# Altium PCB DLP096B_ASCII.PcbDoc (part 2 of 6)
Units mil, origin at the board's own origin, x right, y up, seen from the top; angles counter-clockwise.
Board outline 4950 x 3159.45 mil, 8 copper layers (Top Layer, GND1, SIGNAL1, POWER1, POWER2, SIGNAL2, GND2, Bottom Layer), stack 60.4 mil thick; 327 components, 222 nets, 1374 pads, 853 vias.
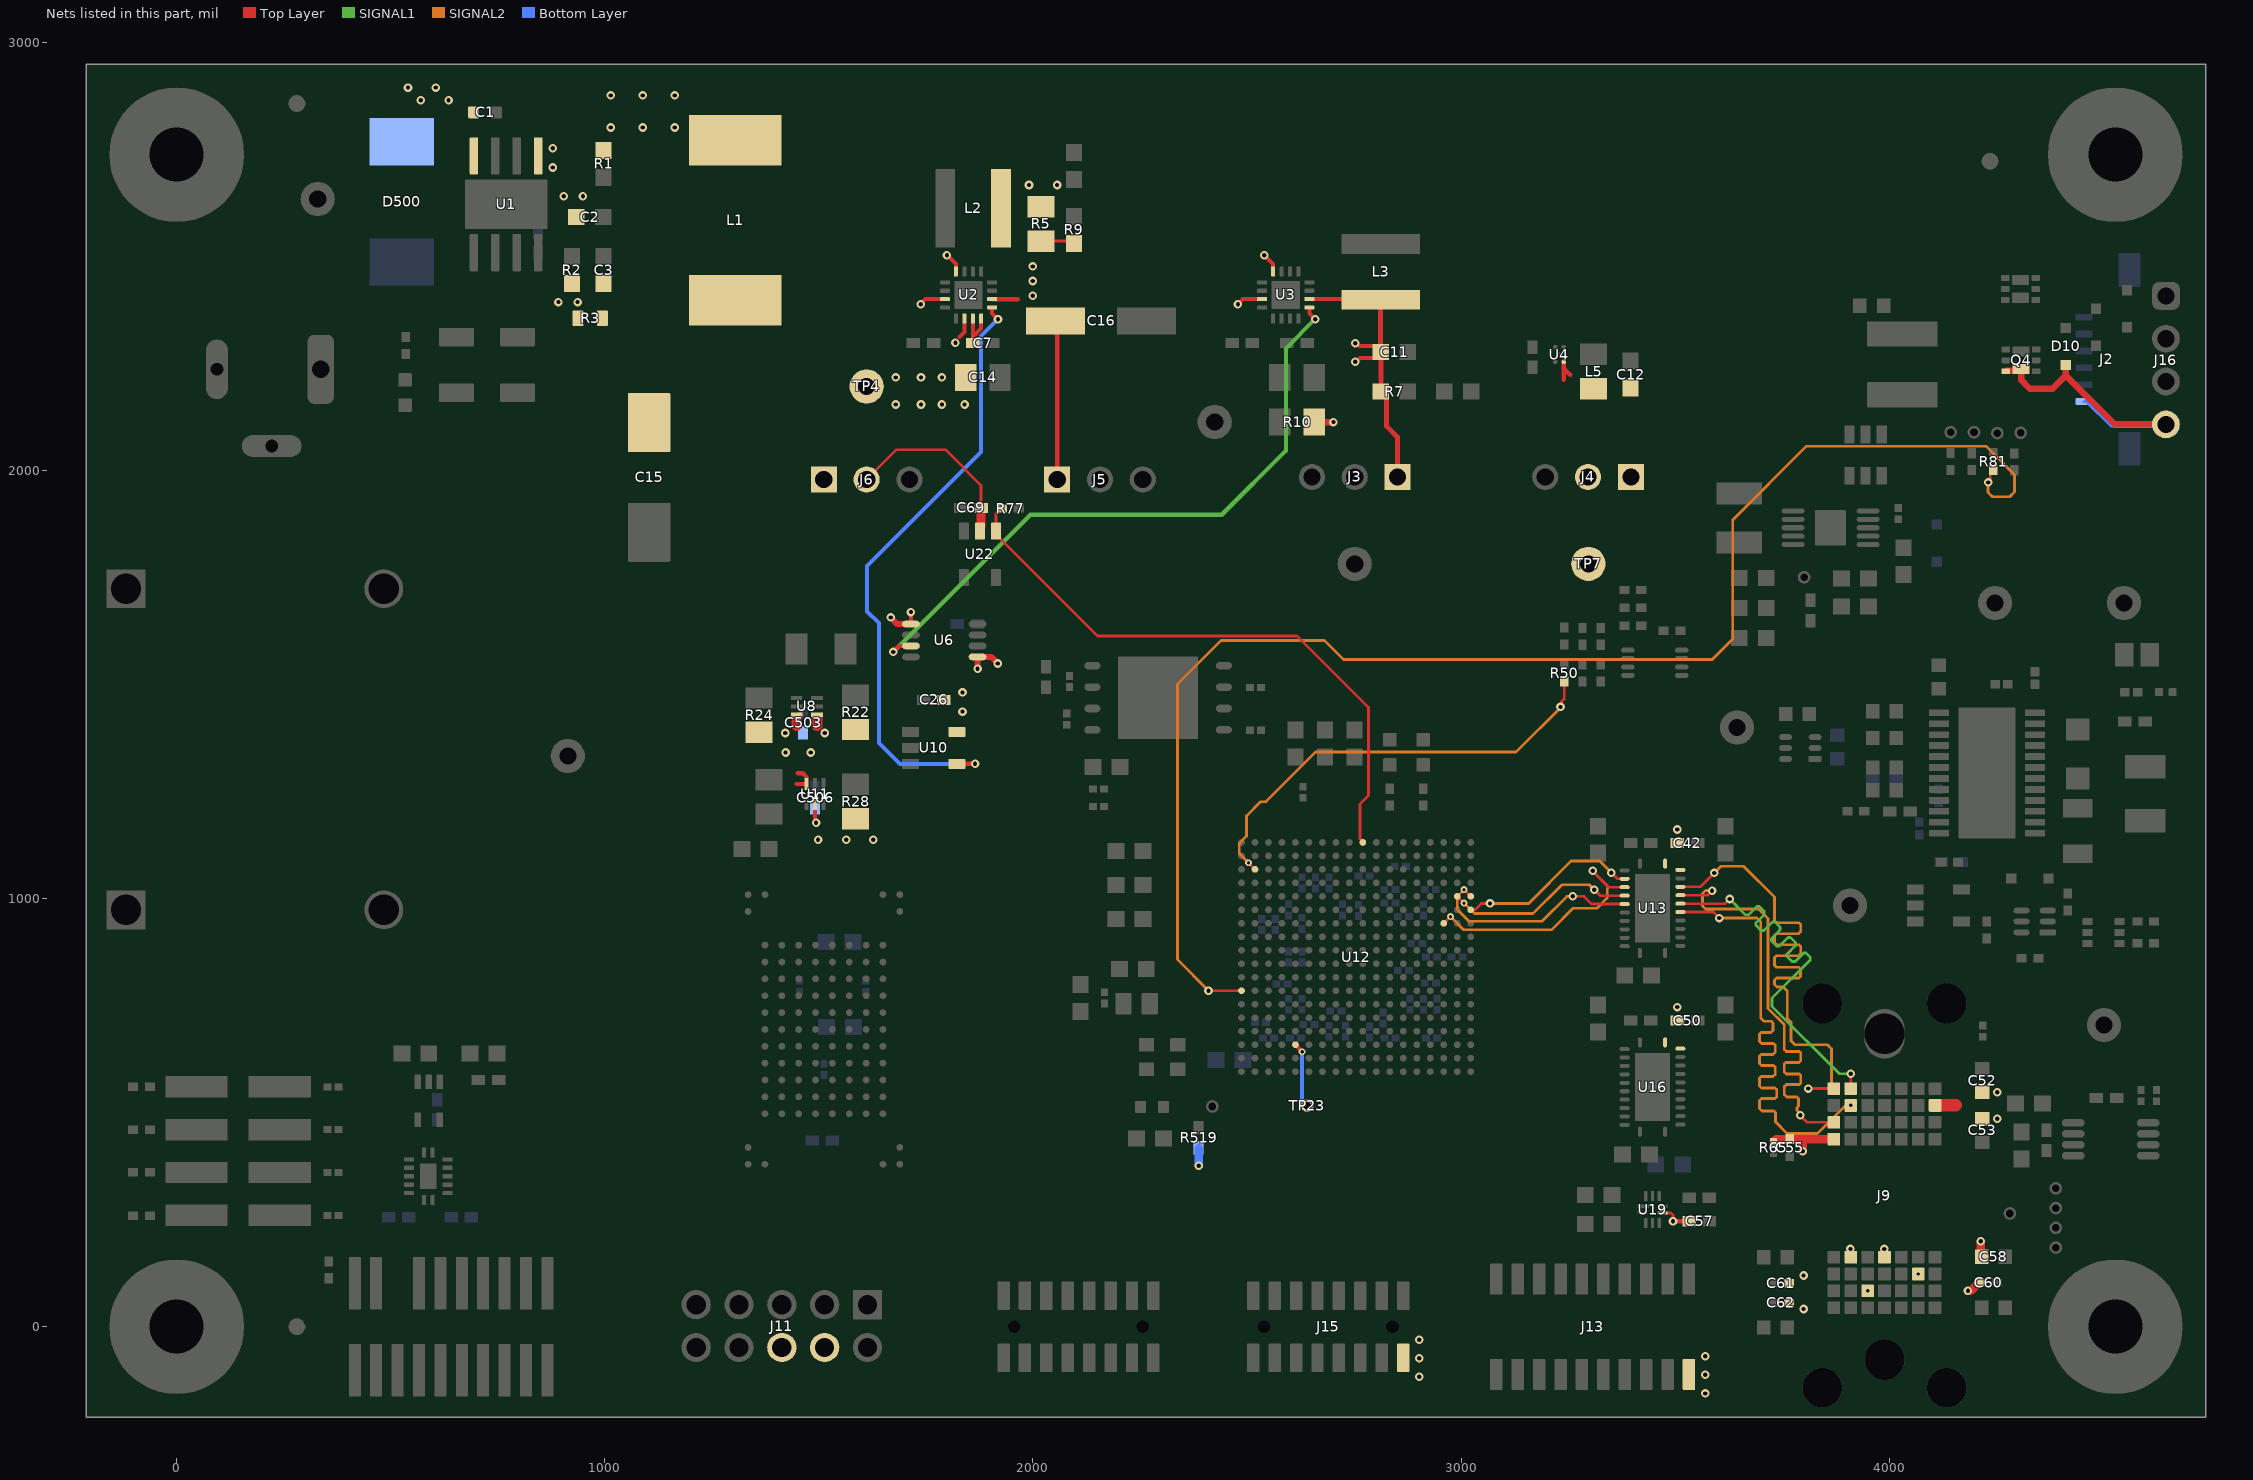
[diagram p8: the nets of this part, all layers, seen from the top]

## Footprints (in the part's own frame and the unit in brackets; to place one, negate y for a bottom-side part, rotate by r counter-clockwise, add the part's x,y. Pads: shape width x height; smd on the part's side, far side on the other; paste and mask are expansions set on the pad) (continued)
CL_800x1000 [mm] "SMD, 2-Leads, Dia 8mm"
  rrect4% 3.5x2.5 smd: 1(-3.25,0) 2(3.25,0)
DBV0005A_N [mm] "SOT23, 5-Leads, Body 2.9x1.6mm, Pitch 0.95mm, Lead Span 2.8mm, IPC Medium Density"
  rrect17% 1x0.6 smd: 1(-1.375,0.95) 2(-1.375,0) 3(-1.375,-0.95) 4(1.375,-0.95) 5(1.375,0.95)
  silkscreen extent -0.25,-1.55 0.25,1.55
DCK0005A_N [mm] "SOT353, 5-Leads, Body 2x1.3mm, Pitch 0.65mm, Lead Span 2.1mm, IPC Medium Density"
  rrect25% 0.85x0.4 smd: 1(-1.125,0.65) 2(-1.125,0) 3(-1.125,-0.65) 4(1.125,-0.65) 5(1.125,0.65)
  silkscreen extent -1.48,-1.03 0.55,1.1
DCT0008A_N [mm] "TSOP, 8-Leads, Body 3x2.8mm, Pitch 0.65mm, IPC Medium Density"
  oval 1.05x0.4 smd: 1(-1.975,0.975) 2(-1.975,0.325) 3(-1.975,-0.325) 4(-1.975,-0.975) 5(1.975,-0.975) 6(1.975,-0.325) 7(1.975,0.325) 8(1.975,0.975)
  silkscreen extent -2.32,-1.57 0.6,1.58
DCU0008A_N [mm] "TSSOP, 8-Leads, Body 2x2.3mm, Pitch 0.5mm, IPC Medium Density"
  oval 0.8x0.3 smd: 1(-1.6,0.75) 2(-1.6,0.25) 3(-1.6,-0.25) 4(-1.6,-0.75) 5(1.6,-0.75) 6(1.6,-0.25) 7(1.6,0.25) 8(1.6,0.75)
  silkscreen extent -1.05,-1.05 0.38,1.05
DDA0008E-MFG [mm]
  rrect20% 2.2x0.5 smd paste-1000 mask+0: 1(-2.875,1.905) 2(-2.875,0.635) 3(-2.875,-0.635) 4(-2.875,-1.905) 5(2.875,-1.905) 6(2.875,-0.635) 7(2.875,0.635) 8(2.875,1.905)
  rrect3% 2.95x4.9 smd paste-1000 mask+0: 9(0,0)
  silkscreen extent -4.67,-2.83 2,2.83
DGK0008A_N [mm] "TSOP, 8-Leads, Body 3x3mm, Pitch 0.65mm, IPC Medium Density"
  oval 1.35x0.45 smd: 1(-2.225,0.975) 2(-2.225,0.325) 3(-2.225,-0.325) 4(-2.225,-0.975) 5(2.225,-0.975) 6(2.225,-0.325) 7(2.225,0.325) 8(2.225,0.975)
  silkscreen extent -2.75,-1.55 0.95,1.55
DGQ0010E_N [mm] "TSSOP, 10-Leads, Body 3x3mm, Pitch 0.5mm, Thermal Pad 1.83x2.1mm, IPC Medium Density"
  rrect100% 1.35x0.3 smd: 1(-2.225,1) 2(-2.225,0.5) 3(-2.225,0) 4(-2.225,-0.5) 5(-2.225,-1) 6(2.225,-1) 7(2.225,-0.5) 8(2.225,0) 9(2.225,0.5) 10(2.225,1)
  rrect5% 1.83x2.1 smd: 11(0,0)
  silkscreen extent -2.73,-1.55 0.9,1.55
DO-219AB [mm] "Vishay Semiconductor"
  rrect8% 1.3x1.4 smd: 1(-1.45,0) 2(1.45,0)
  silkscreen extent -1.9,-1.07 1.23,1.07
DSE0006A [mm] "TI recommended land pattern"
  rect 0.66x0.25 smd: 1(-0.62,0.5)
  rect 0.7x0.25 smd: 2(-0.6,0) 3(-0.6,-0.5) 4(0.6,-0.5) 5(0.6,0) 6(0.6,0.5)
  silkscreen extent -0.9,-0.92 0.9,0.92
ECS_ECS-2520S [mm] "SMD, 4-Leads, Body 2x2.5mm"
  rrect12% 0.8x0.9 smd: 1(-0.725,0.925) 2(-0.725,-0.925) 3(0.725,-0.925) 4(0.725,0.925)
  silkscreen extent -1.7,0.9 -1.5,1.1
FCC_disclaimer [mil]
FDSD0420 [mm] "SMD, 2-Leads, Body 4.2x4.2mm"
  rect 1.4x2.4 smd: 1(-1.6,0) 2(1.6,0)
  silkscreen extent -2.2,-2.2 2.2,2.2
Fiducial10-20#1 [mm]
  round 1 smd mask+0: 1(0,0)
  Top Layer keep-out circle w1.178: c0,0 r0.5
Fiducial10-20#2 [mm]
  round 1 smd mask+0.5: 1(0,0)
  Top Layer keep-out circle w1.178: c0,0 r0.5
FP-2516672_SMD_CONN_LGA-56-MFG [mm]
  rrect13% 0.75x0.75 smd paste-1000 mask+0: A2(6.3,3) A3(5.3,3) A4(4.3,3) A5(3.3,3) A12(-3.7,3) A13(-4.7,3) A14(-5.7,3) A15(-6.7,3) B2(6.3,2) B3(5.3,2) B4(4.3,2) B5(3.3,2) B12(-3.7,2) B13(-4.7,2) B14(-5.7,2) B15(-6.7,2) C2(6.3,1) C3(5.3,1) C4(4.3,1) C5(3.3,1) C12(-3.7,1) C13(-4.7,1) C14(-5.7,1) C15(-6.7,1) D2(6.3,0) D3(5.3,0) D4(4.3,0) D5(3.3,0) D12(-3.7,0) D13(-4.7,0) D14(-5.7,0) D15(-6.7,0) E2(6.3,-1) E3(5.3,-1) E4(4.3,-1) E5(3.3,-1) E12(-3.7,-1) E13(-4.7,-1) E14(-5.7,-1) E15(-6.7,-1) F2(6.3,-2) F3(5.3,-2) F4(4.3,-2) F5(3.3,-2) F12(-3.7,-2) F13(-4.7,-2) F14(-5.7,-2) F15(-6.7,-2) G2(6.3,-3) G3(5.3,-3) G4(4.3,-3) G5(3.3,-3) G12(-3.7,-3) G13(-4.7,-3) G14(-5.7,-3) G15(-6.7,-3)
  round 2.35 hole 2.35 unplated paste-1000: ""(-11.45,-3.7) ""(-11.45,3.7) ""(11.35,-3.7) ""(11.35,3.7)
  round 2.4 hole 2.4 unplated paste-1000: ""(-9.8,0)
  rrect100% 2.95x2.4 hole 2.4 slot 2.95 at 0 deg unplated paste-1000: ""(9.55,0)
  silkscreen extent -11.86,-4.5 11.86,4.5
FP-702461002_HDR10-MFG [mm]
  rrect6% 1.74x1.74 hole 1.14 paste-1000 mask+0: 1(-5.08,-1.275)
  round 1.74 hole 1.14 paste-1000 mask+0: 2(-5.08,1.265) 3(-2.54,-1.275) 4(-2.54,1.265) 5(0,-1.275) 6(0,1.265) 7(2.54,-1.275) 8(2.54,1.265) 9(5.08,-1.275) 10(5.08,1.265)
  silkscreen extent -10.26,-5.34 10.26,4.54
FP-2005280060_CONN_11MM2_5MM25-MFG [mm]
  rrect25% 0.4x1 smd paste+0 mask+0: 1(-2.5,2.475) 2(-1.5,2.475) 3(-0.5,2.475) 4(0.5,2.475) 5(1.5,2.475) 6(2.5,2.475)
  rrect8% 2x1.3 smd paste+0 mask+0: 7(-5.3,-0.225) 8(5.3,-0.225)
  silkscreen extent -5.7,-2.73 5.7,3.67
FP-BAT54XYH_SOT363-IPC_C [mm]
  rrect29% 0.759x0.342 smd: 1(-0.877,0.65)
  rrect100% 0.759x0.342 smd: 2(-0.877,0) 3(-0.877,-0.65) 4(0.877,-0.65) 5(0.877,0) 6(0.877,0.65)
  silkscreen extent -1.96,-1 0.12,1
FP-BLM18EG121SN1D_0603-MFG [mm]
  rrect15% 0.65x0.7 smd paste+0 mask+0: 1(-0.675,0) 2(0.675,0)
  silkscreen extent -0.88,-0.8 0.88,0.8
FP-CR0603-FX-3163ELF_0603-MFG [mm]
  rrect15% 0.65x0.9 smd: 1(-0.725,0) 2(0.725,0)
  silkscreen extent 0,-0.45 0,0.45
FP-ERA-2AEB104X_0402-IPC_C [mil]
  rrect19% 22.03x20.31 smd: 1(-14.81,0) 2(14.81,0)
  silkscreen extent -26,-28 26,28
FP-ERA-2AEB822X_0402-IPC_C [mil]
  rrect19% 22.03x20.31 smd: 1(-14.81,0) 2(14.81,0)
  silkscreen extent -26,-28 26,28
FP-ERA-2AEB1212X_0402-IPC_C [mil]
  rrect19% 22.03x20.31 smd: 1(-14.81,0) 2(14.81,0)
  silkscreen extent -26,-28 26,28
FP-FTR-110-03-G-D-06_HDR19-MFG [mil]
  rrect14% 28x123 smd paste+0 mask+0: 1(-225,-101.5) 2(-225,101.5) 3(-175,-101.5) 4(-175,101.5) 5(-125,-101.5) 7(-75,-101.5) 8(-75,101.5) 9(-25,-101.5) 10(-25,101.5) 11(25,-101.5) 12(25,101.5) 13(75,-101.5) 14(75,101.5) 15(125,-101.5) 16(125,101.5) 17(175,-101.5) 18(175,101.5) 19(225,-101.5) 20(225,101.5)
  silkscreen extent -266,-131 251,101
FP-GCJ32DL8EL225KA07L_1210-MFG [mm]
  rrect9% 1.1x2.05 smd paste+0 mask+0: 1(-1.65,0) 2(1.65,0)
  silkscreen extent -1.8,-1.4 1.8,1.4
FP-GCM188L81H104KA57D_0603-MFG [mm]
  rrect15% 0.65x0.7 smd paste+0 mask+0: 1(-0.675,0) 2(0.675,0)
FP-LSL29K-G1H2-1-Z_0603-0 [mm]
  rrect13% 0.8x0.8 smd paste-1000 mask+0: 1(-0.75,0) 2(0.75,0)
  silkscreen extent -1.77,-0.77 0.7,0.77
FP-MTFC128GAPALNA-AAT_TBGA100-MFG [mm]
  round 0.4 smd: A1(-4.5,8) A2(-3.5,8) A9(3.5,8) A10(4.5,8) B1(-4.5,7) B10(4.5,7) D2(-3.5,5) D3(-2.5,5) D4(-1.5,5) D5(-0.5,5) D6(0.5,5) D7(1.5,5) D8(2.5,5) D9(3.5,5) E2(-3.5,4) E3(-2.5,4) E4(-1.5,4) E5(-0.5,4) E6(0.5,4) E7(1.5,4) E8(2.5,4) E9(3.5,4) F2(-3.5,3) F3(-2.5,3) F4(-1.5,3) F5(-0.5,3) F6(0.5,3) F7(1.5,3) F8(2.5,3) F9(3.5,3) G2(-3.5,2) G3(-2.5,2) G4(-1.5,2) G5(-0.5,2) G6(0.5,2) G7(1.5,2) G8(2.5,2) G9(3.5,2) H2(-3.5,1) H3(-2.5,1)
  round 0.4 smd paste+0 mask+0: H4(-1.5,1) H5(-0.5,1) H6(0.5,1) H7(1.5,1) H8(2.5,1) H9(3.5,1) J2(-3.5,0) J3(-2.5,0) J4(-1.5,0) J5(-0.5,0) J6(0.5,0) J7(1.5,0) J8(2.5,0) J9(3.5,0) K2(-3.5,-1) K3(-2.5,-1) K4(-1.5,-1) K5(-0.5,-1) K6(0.5,-1) K7(1.5,-1) K8(2.5,-1) K9(3.5,-1) L2(-3.5,-2) L3(-2.5,-2) L4(-1.5,-2) L5(-0.5,-2) L6(0.5,-2) L7(1.5,-2) L8(2.5,-2) L9(3.5,-2) M2(-3.5,-3) M3(-2.5,-3) M4(-1.5,-3) M5(-0.5,-3) M6(0.5,-3) M7(1.5,-3) M8(2.5,-3) M9(3.5,-3) N2(-3.5,-4) N3(-2.5,-4) N4(-1.5,-4) N5(-0.5,-4) N6(0.5,-4) N7(1.5,-4) N8(2.5,-4) N9(3.5,-4) P2(-3.5,-5) P3(-2.5,-5) P4(-1.5,-5) P5(-0.5,-5) P6(0.5,-5) P7(1.5,-5) P8(2.5,-5) P9(3.5,-5) T1(-4.5,-7) T10(4.5,-7) U1(-4.5,-8) U2(-3.5,-8) U9(3.5,-8) U10(4.5,-8)
  silkscreen extent -7.67,-9.05 7.05,9.05
FP-NX3008NBKS,115_TSSOP6-IPC_C [mm]
  rrect29% 0.959x0.342 smd: 1(-0.777,0.65)
  rrect100% 0.959x0.342 smd: 2(-0.777,0) 3(-0.777,-0.65) 4(0.777,-0.65) 5(0.777,0) 6(0.777,0.65)
  silkscreen extent -1.88,-1.25 1.05,1.25
FP-RMCF0805ZT0R00_0805-IPC_C [mil]
  rrect10% 37.58x49.69 smd paste+0 mask+0: 1(-30.54,0) 2(30.54,0)
  silkscreen extent -49,-42 49,42
FP-S25FL128SAGNFI000_WSON8-MFG [mm]
  rrect100% 0.95x0.45 smd: 1(-3.9,1.905) 2(-3.9,0.635) 3(-3.9,-0.635) 4(-3.9,-1.905) 5(3.9,-1.905) 6(3.9,-0.635) 7(3.9,0.635) 8(3.9,1.905)
  rrect2% 4.75x4.9 smd: 9(0,0)
  silkscreen extent -5.05,-3.05 4.05,3.05
FP-TNPW040215K6BEED_0402-IPC_C [mil]
  rrect21% 18.32x18.6 smd: 1(-15.89,0) 2(15.89,0)
  silkscreen extent -25,-27 25,27
Harwin_M7582-05 [mil] "Single Operation 2.54mm Pitch Open Top Jumper Socket"
Keystone5001 [mil] "For Keystone 500x miniature loop terminals"
  round 80 hole 40: 1(0,0)
  silkscreen extent -52,-52 52,52
Keystone_1902C [mil] "Hex Standoff, 4-40 threaded, nylon"
  round 1 on Mech4: 0(0,0)
Label_650x200 [mil] "Thermal Transfer Label"
  round 1 on Mech13: 0(0,0)
  silkscreen extent -325,-100 325,100
Memory_EJ508A [mm] "Power Jack, 2.1x5.5mm, R/A, TH"
  rrect50% 4.1x1.55 hole 1.02 square: 1(0,2.91)
  oval 3.55x1.3 hole 0.76 square: 2(0,-3.25)
  oval 1.3x3.55 hole 0.76 square: 3(4.55,0)
  silkscreen extent -4.4,-10.74 4.4,3.16
Molex_0022284033 [mm] "Header, 2.54mm, 3x1, TH"
  rect 1.55x1.55 hole 1.02: 1(-2.54,0)
  round 1.55 hole 1.02: 2(0,0) 3(2.54,0)
  silkscreen extent -3.81,-1.24 3.81,1.5
MSS1210 [mm] "Coilcraft MSS1210 series"
  rect 3x5.5 smd: 1(-4.75,0) 2(4.75,0)
  silkscreen extent -6.3,-6.3 6.3,6.3
"NY PMS 440 0025 PH" [mm] "4-40 nylon screw and mounting hole"
  round 8 hole 3.2: 1(0,0)
PWP0024B_NV_L [mm] "TSOP, 24-Leads, Body 7.9x4.5mm (max), Pitch 0.65mm, IPC High Density"
  rrect25% 1.2x0.4 smd: 1(-2.85,3.575) 2(-2.85,2.925) 3(-2.85,2.275) 4(-2.85,1.625) 5(-2.85,0.975) 6(-2.85,0.325) 7(-2.85,-0.325) 8(-2.85,-0.975) 9(-2.85,-1.625) 10(-2.85,-2.275) 11(-2.85,-2.925) 12(-2.85,-3.575) 13(2.85,-3.575) 14(2.85,-2.925) 15(2.85,-2.275) 16(2.85,-1.625) 17(2.85,-0.975) 18(2.85,-0.325) 19(2.85,0.325) 20(2.85,0.975) 21(2.85,1.625) 22(2.85,2.275) 23(2.85,2.925) 24(2.85,3.575)
  rrect6% 3.4x7.8 smd paste-2 mask+0: 25(0,0)
  rrect4% 2.4x5.16 on Top Paste: 25(0,0)
  rrect4% 2.4x5.16 on Top Solder: 25(0,0)
  silkscreen extent -2,-3.95 1.7,3.95
RGT0016C [mm] "QFN, 16-Leads, Body 3x3mm, Pitch 0.5mm, Thermal Pad 1.7x1.7mm, TI Recommended"
  rrect42% 0.6x0.24 smd: 1(-1.4,0.75) 2(-1.4,0.25) 3(-1.4,-0.25) 4(-1.4,-0.75) 9(1.4,-0.75) 10(1.4,-0.25) 11(1.4,0.25) 12(1.4,0.75)
  rrect42% 0.24x0.6 smd: 5(-0.75,-1.4) 6(-0.25,-1.4) 7(0.25,-1.4) 8(0.75,-1.4) 13(0.75,1.4) 14(0.25,1.4) 15(-0.25,1.4) 16(-0.75,1.4)
  rrect6% 1.55x1.55 on Top Paste: 17(0,0)
  rrect6% 1.68x1.68 smd paste-0.85: 17(0,0)
  silkscreen extent -1.72,-1.73 1.73,1.73
RHL0024A [mm]
  oval 0.24x0.6 smd: 1(-0.75,2.65) 12(-0.75,-2.65) 13(0.75,-2.65) 24(0.75,2.65)
  oval 0.6x0.24 smd: 2(-1.65,2.25) 3(-1.65,1.75) 4(-1.65,1.25) 5(-1.65,0.75) 6(-1.65,0.25) 7(-1.65,-0.25) 8(-1.65,-0.75) 9(-1.65,-1.25) 10(-1.65,-1.75) 11(-1.65,-2.25) 14(1.65,-2.225) 15(1.65,-1.725) 16(1.65,-1.225) 17(1.65,-0.725) 18(1.65,-0.225) 19(1.65,0.275) 20(1.65,0.775) 21(1.65,1.275) 22(1.65,1.775) 23(1.65,2.275)
  rect 2.05x4.05 smd paste-1.1: 25(0,0)
  Top Layer region: 0.396,-2 0.154,-2 0.154,-2.75 0.396,-2.75
  Top Layer region: -0.152,-2 -0.394,-2 -0.394,-2.75 -0.152,-2.75
  Top Layer region: -0.395,2.024 0.395,2.024 0.395,2.225 -0.395,2.225
  Top Layer region: 0.152,2 0.394,2 0.394,2.75 0.152,2.75
  Top Layer region: -0.396,2 -0.154,2 -0.154,2.75 -0.396,2.75
  Top Layer region: -0.395,-2.225 0.395,-2.225 0.395,-2.024 -0.395,-2.024
  silkscreen extent -1.95,-2.95 1.95,2.95
RSW0010A [mm] "QFN, 10-Leads, Body 1.8x1.4 mm, Pitch 0.4mm, TI Recommended"
  rrect50% 0.7x0.2 smd: 1(-0.55,0.2)
  rrect50% 0.6x0.2 smd: 2(-0.6,-0.2) 6(0.6,-0.2) 7(0.6,0.2)
  rrect50% 0.2x0.6 smd: 3(-0.4,-0.8) 4(0,-0.8) 5(0.4,-0.8) 8(0.4,0.8) 9(0,0.8) 10(-0.4,0.8)
  silkscreen extent -0.88,-1.08 0.88,1.08
Samtec_FLE-108-01-x-DV-A [mm] "Receptacle, 1.27mm, 8x2, SMT"
  rrect14% 0.74x1.675 smd: 1(-4.445,1.843) 2(-4.445,-1.842) 3(-3.175,1.843) 4(-3.175,-1.842) 5(-1.905,1.843) 6(-1.905,-1.842) 7(-0.635,1.843) 8(-0.635,-1.842) 9(0.635,1.843) 10(0.635,-1.842) 11(1.905,1.843) 12(1.905,-1.842) 13(3.175,1.843) 14(3.175,-1.842) 15(4.445,1.843) 16(4.445,-1.842)
  round 0.46 hole 0.76 unplated: ""(-3.81,0) ""(3.81,0)
  silkscreen extent -5.5,-1.5 5.2,1.5
Samtec_RSM-110-02-x-D [mm] "Receptacle, 1.27mm, 10x2, SMT"
  rrect14% 0.74x1.84 smd: 1(-5.715,2.825) 2(-5.715,-2.825) 3(-4.445,2.825) 4(-4.445,-2.825) 5(-3.175,2.825) 6(-3.175,-2.825) 7(-1.905,2.825) 8(-1.905,-2.825) 9(-0.635,2.825) 10(-0.635,-2.825) 11(0.635,2.825) 12(0.635,-2.825) 13(1.905,2.825) 14(1.905,-2.825) 15(3.175,2.825) 16(3.175,-2.825) 17(4.445,2.825) 18(4.445,-2.825) 19(5.715,2.825) 20(5.715,-2.825)
Samtec_TSM-104-01-x-DV [mm] "Header, 2.54mm, 4x2, SMT"
  rect 3.68x1.27 smd: 1(-2.475,3.81) 2(2.475,3.81) 3(-2.475,1.27) 4(2.475,1.27) 5(-2.475,-1.27) 6(2.475,-1.27) 7(-2.475,-3.81) 8(2.475,-3.81)
  silkscreen extent -1.65,-5.08 1.65,5.22
SM_RADIAL_6.3BMM [mm] "Nichicon 6.3x7.7"
  rect 3.5x1.6 smd: 1(-2.7,0) 2(2.7,0)
  silkscreen extent -3.4,-3.4 3.4,3.4
SMC [mil] "Molded Diode, 2-Leads, Body 6.9x5.8mm, IPC Medium Density, based on OnSemi component dimensions and land patterns"
  rect 110x150 smd: 1(-140.49,0) 2(140.49,0)
  silkscreen extent -221,-123 189,124
SOD-323#1 [mm] "NXP recommended land pattern"
  rect 0.6x0.6 smd paste-0.05: 1(-1.1,0) 2(1.1,0)
  silkscreen extent -2.06,-0.86 1.53,0.86
SOD-323#2 [mm] "NXP recommended land pattern"
  rect 0.6x0.6 smd: 1(-1.1,0) 2(1.1,0)
  silkscreen extent -2.06,-0.86 1.53,0.86
SOT-26 [mm] "SOT23, 6-Leads, Body 3.1x3.0mm (max), Pitch 0.95mm, IPC Medium Density based on Diodes Inc ap02002.pdf rev 29"
  rect 1.05x0.6 smd: 1(-1.225,0.95) 2(-1.225,0) 3(-1.225,-0.95) 4(1.225,-0.95) 5(1.225,0) 6(1.225,0.95)
  silkscreen extent -0.3,-1.55 0.3,1.55
SOT-363 [mm]
  rect 0.6x0.42 smd: 1(-0.95,0.65) 2(-0.95,0) 3(-0.95,-0.65) 4(0.95,-0.65) 5(0.95,0) 6(0.95,0.65)
  silkscreen extent -0.38,-1.02 0.38,1.02
SRN5040TA [mm] "Bourns"
  rrect7% 1.5x4.2 smd: 1(-1.8,0) 2(1.8,0)
TI_Stacked_Overlay_Small [mil]
TP_H045P075 [mm] "TP_H0.45P0.75"
  round 0.75 hole 0.45: 1(0,0)
TSW-104-07-G-S [mm] "Samtec 100mil, 1x4, 230 mil above insulator"
  rrect50% 1.65x1.65 hole 1.016: 1(-3.81,0)
  round 1.65 hole 1.016: 2(-1.27,0) 3(1.27,0) 4(3.81,0)
U-DFN2020-6_B [mm] "SMD, 6-Leads, Body 2x2mm, Pitch 0.65mm"
  rrect29% 0.5x0.35 smd: 1(-0.9,0.65) 2(-0.9,0) 3(-0.9,-0.65) 4(0.9,-0.65) 5(0.9,0) 6(0.9,0.65)
  rrect17% 1x0.6 smd: 7(0,0.525) 8(0,-0.525)
  silkscreen extent -1.04,-1.19 1.04,1.4
WEEE_Minimum [mil] "WEEElie bin"
  silkscreen extent 22,-71 54,74
XAL5030 [mil] "Coilcraft XAL5030 12/12/11"
  rect 46x183 smd: 1(-65,0) 2(65,0)
  silkscreen extent -108,-112 108,112
YZR0005AEBA [mm] "Micro SMD, 5-Leads, Body 1.39x1.06mm, Pitch 0.5mm, NSC Recommended"
  round 0.265 smd paste-0.132 mask+0: A1(-0.25,0.433) A3(0.25,0.433) B2(0,0) C1(-0.25,-0.433) C3(0.25,-0.433)
  silkscreen extent -0.68,0.75 -0.58,0.85
ZCZ0324A-MFG [mm]
  round 0.4 smd paste+0 mask+0: A1(-6.8,6.8) A2(-6,6.8) A3(-5.2,6.8) A4(-4.4,6.8) A5(-3.6,6.8) A6(-2.8,6.8) A7(-2,6.8) A8(-1.2,6.8) A9(-0.4,6.8) A10(0.4,6.8) A11(1.2,6.8) A12(2,6.8) A13(2.8,6.8) A14(3.6,6.8) A15(4.4,6.8) A16(5.2,6.8) A17(6,6.8) A18(6.8,6.8) B1(-6.8,6) B2(-6,6) B3(-5.2,6) B4(-4.4,6) B5(-3.6,6) B6(-2.8,6) B7(-2,6) B8(-1.2,6) B9(-0.4,6) B10(0.4,6) B11(1.2,6) B12(2,6) B13(2.8,6) B14(3.6,6) B15(4.4,6) B16(5.2,6) B17(6,6) B18(6.8,6) C1(-6.8,5.2) C2(-6,5.2) C3(-5.2,5.2) C4(-4.4,5.2) C5(-3.6,5.2) C6(-2.8,5.2) C7(-2,5.2) C8(-1.2,5.2) C9(-0.4,5.2) C10(0.4,5.2) C11(1.2,5.2) C12(2,5.2) C13(2.8,5.2) C14(3.6,5.2) C15(4.4,5.2) C16(5.2,5.2) C17(6,5.2) C18(6.8,5.2) D1(-6.8,4.4) D2(-6,4.4) D3(-5.2,4.4) D4(-4.4,4.4) D5(-3.6,4.4) D6(-2.8,4.4) D7(-2,4.4) D8(-1.2,4.4) D9(-0.4,4.4) D10(0.4,4.4) D11(1.2,4.4) D12(2,4.4) D13(2.8,4.4) D14(3.6,4.4) D15(4.4,4.4) D16(5.2,4.4) D17(6,4.4) D18(6.8,4.4) E1(-6.8,3.6) E2(-6,3.6) E3(-5.2,3.6) E4(-4.4,3.6) E5(-3.6,3.6) E6(-2.8,3.6) E7(-2,3.6) E8(-1.2,3.6) E9(-0.4,3.6) E10(0.4,3.6) E11(1.2,3.6) E12(2,3.6) E13(2.8,3.6) E14(3.6,3.6) E15(4.4,3.6) E16(5.2,3.6) E17(6,3.6) E18(6.8,3.6) F1(-6.8,2.8) F2(-6,2.8) F3(-5.2,2.8) F4(-4.4,2.8) F5(-3.6,2.8) F6(-2.8,2.8) F7(-2,2.8) F8(-1.2,2.8) F9(-0.4,2.8) F10(0.4,2.8) F11(1.2,2.8) F12(2,2.8) F13(2.8,2.8) F14(3.6,2.8) F15(4.4,2.8) F16(5.2,2.8) F17(6,2.8) F18(6.8,2.8) G1(-6.8,2) G2(-6,2) G3(-5.2,2) G4(-4.4,2) G5(-3.6,2) G6(-2.8,2) G7(-2,2) G8(-1.2,2) G9(-0.4,2) G10(0.4,2) G11(1.2,2) G12(2,2) G13(2.8,2) G14(3.6,2) G15(4.4,2) G16(5.2,2) G17(6,2) G18(6.8,2) H1(-6.8,1.2) H2(-6,1.2) H3(-5.2,1.2) H4(-4.4,1.2) H5(-3.6,1.2) H6(-2.8,1.2) H7(-2,1.2) H8(-1.2,1.2) H9(-0.4,1.2) H10(0.4,1.2) H11(1.2,1.2) H12(2,1.2) H13(2.8,1.2) H14(3.6,1.2) H15(4.4,1.2) H16(5.2,1.2) H17(6,1.2) H18(6.8,1.2) J1(-6.8,0.4) J2(-6,0.4) J3(-5.2,0.4) J4(-4.4,0.4) J5(-3.6,0.4) J6(-2.8,0.4) J7(-2,0.4) J8(-1.2,0.4) J9(-0.4,0.4) J10(0.4,0.4) J11(1.2,0.4) J12(2,0.4) J13(2.8,0.4) J14(3.6,0.4) J15(4.4,0.4) J16(5.2,0.4) J17(6,0.4) J18(6.8,0.4) K1(-6.8,-0.4) K2(-6,-0.4) K3(-5.2,-0.4) K4(-4.4,-0.4) K5(-3.6,-0.4) K6(-2.8,-0.4) K7(-2,-0.4) K8(-1.2,-0.4) K9(-0.4,-0.4) K10(0.4,-0.4) K11(1.2,-0.4) K12(2,-0.4) K13(2.8,-0.4) K14(3.6,-0.4) K15(4.4,-0.4) K16(5.2,-0.4) K17(6,-0.4) K18(6.8,-0.4) L1(-6.8,-1.2) L2(-6,-1.2) L3(-5.2,-1.2) L4(-4.4,-1.2) L5(-3.6,-1.2) L6(-2.8,-1.2) L7(-2,-1.2) L8(-1.2,-1.2) L9(-0.4,-1.2) L10(0.4,-1.2) L11(1.2,-1.2) L12(2,-1.2) L13(2.8,-1.2) L14(3.6,-1.2) L15(4.4,-1.2) L16(5.2,-1.2) L17(6,-1.2) L18(6.8,-1.2) M1(-6.8,-2) M2(-6,-2) M3(-5.2,-2) M4(-4.4,-2) M5(-3.6,-2) M6(-2.8,-2) M7(-2,-2) M8(-1.2,-2) M9(-0.4,-2) M10(0.4,-2) M11(1.2,-2) M12(2,-2) M13(2.8,-2) M14(3.6,-2) M15(4.4,-2) M16(5.2,-2) M17(6,-2) M18(6.8,-2) N1(-6.8,-2.8) N2(-6,-2.8) N3(-5.2,-2.8) N4(-4.4,-2.8) N5(-3.6,-2.8) N6(-2.8,-2.8) N7(-2,-2.8) N8(-1.2,-2.8) N9(-0.4,-2.8) N10(0.4,-2.8) N11(1.2,-2.8) N12(2,-2.8) N13(2.8,-2.8) N14(3.6,-2.8) N15(4.4,-2.8) N16(5.2,-2.8) N17(6,-2.8) N18(6.8,-2.8) P1(-6.8,-3.6) P2(-6,-3.6) P3(-5.2,-3.6) P4(-4.4,-3.6) P5(-3.6,-3.6) P6(-2.8,-3.6) P7(-2,-3.6) P8(-1.2,-3.6) P9(-0.4,-3.6) P10(0.4,-3.6) P11(1.2,-3.6) P12(2,-3.6) P13(2.8,-3.6) P14(3.6,-3.6) P15(4.4,-3.6) P16(5.2,-3.6) P17(6,-3.6) P18(6.8,-3.6) R1(-6.8,-4.4) R2(-6,-4.4) R3(-5.2,-4.4) R4(-4.4,-4.4) R5(-3.6,-4.4) R6(-2.8,-4.4) R7(-2,-4.4) R8(-1.2,-4.4) R9(-0.4,-4.4) R10(0.4,-4.4) R11(1.2,-4.4) R12(2,-4.4) R13(2.8,-4.4) R14(3.6,-4.4) R15(4.4,-4.4) R16(5.2,-4.4) R17(6,-4.4) R18(6.8,-4.4) T1(-6.8,-5.2) T2(-6,-5.2) T3(-5.2,-5.2) T4(-4.4,-5.2) T5(-3.6,-5.2) T6(-2.8,-5.2) T7(-2,-5.2) T8(-1.2,-5.2) T9(-0.4,-5.2) T10(0.4,-5.2) T11(1.2,-5.2) T12(2,-5.2) T13(2.8,-5.2) T14(3.6,-5.2) T15(4.4,-5.2) T16(5.2,-5.2) T17(6,-5.2) T18(6.8,-5.2) U1(-6.8,-6) U2(-6,-6) U3(-5.2,-6) U4(-4.4,-6) U5(-3.6,-6) U6(-2.8,-6) U7(-2,-6) U8(-1.2,-6) U9(-0.4,-6) U10(0.4,-6) U11(1.2,-6) U12(2,-6) U13(2.8,-6) U14(3.6,-6) U15(4.4,-6) U16(5.2,-6) U17(6,-6) U18(6.8,-6) V1(-6.8,-6.8) V2(-6,-6.8) V3(-5.2,-6.8) V4(-4.4,-6.8) V5(-3.6,-6.8) V6(-2.8,-6.8) V7(-2,-6.8) V8(-1.2,-6.8) V9(-0.4,-6.8) V10(0.4,-6.8) V11(1.2,-6.8) V12(2,-6.8) V13(2.8,-6.8) V14(3.6,-6.8) V15(4.4,-6.8) V16(5.2,-6.8) V17(6,-6.8) V18(6.8,-6.8)
  silkscreen extent -8.15,-7.55 7.55,7.55

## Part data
C1: library part CMP-0086535-1, "0.1µF ±10% 50V Ceramic Capacitor X8L 0603 (1608 Metric)"
C2: library part CMP-0006792-3, "CAP, CERM, 56 pF, 50 V, +/- 1%, C0G/NP0, 0603"
C3: library part CMP-0007180-1, "CAP, CERM, 1200 pF, 50 V, +/- 5%, C0G/NP0, 0603"
C4 C5: library part CMP-0089367-1, "2.2µF ±10% 100V Ceramic Capacitor X8L 1210 (3225 Metric)"
C6: library part CMP-0080703-2, "CAP, CERM, 390 pF, 50 V,+/- 10%, X7R, AEC-Q200 Grade 1, 0402"
C7 C9 C26 C65 C69 C501 C503 C506 C507 C555 C556 C557: library part CMP-0078241-1, "CAP, CERM, 0.1 µF, 10 V,+/- 10%, X7R, 0402"
C8: library part CMP-0006310-2, "CAP, CERM, 150 pF, 50 V, +/- 5%, C0G/NP0, AEC-Q200 Grade 1, 0402"
C10: library part CMP-0080385-1, "CAP, CERM, 4.7 µF,  VAC/6.3 VDC,+/- 20%, X5R, 0402"
C11 C12 C51: library part CMP-0078295-1, "CAP, CERM, 22 µF, 6.3 V,+/- 20%, X5R, 0603"
C13 C14: library part CMP-0085574-1, "CAP, CERM, 10 µF, 10 V,+80/-20%, Y5V, 0805"
C15: library part CMP-0081924-1, "CAP, AL, 330 µF, 10 V, +/- 20%, SMD"
C16: library part CMP-0011112-1, "CAP, AL, 220 uF, 10 V, +/- 20%, 0.34 ohm, SMD"
C17 C35 C36 C48 C508 C509 C510 C511 C512 C514 C515 C516 C517 C518 C519 C520 C522 C523 C524 C525 C527 C528 C529 C530 C531 C532 C533 C534 C535 C536 C537 C538 C539 C540 C541 C542 C543 C545 C546 C547 C548 C549 C550 C551 C552 C553: library part CMP-0086059-1, "CAP, CERM, 0.1 µF, 10 V,+/- 10%, X5R, 0201"
C18 C526: library part CMP-0079607-1, "CAP, CERM, 1 µF, 16 V,+/- 10%, X7R, AEC-Q200 Grade 1, 0603"
C19 C22 C23 C38 C54 C544: library part CMP-0007022-5, "CAP, CERM, 4.7 uF, 35 V, +/- 10%, X5R, 0603"
C20 C66 C68: library part CMP-0006350-2, "CAP, CERM, 0.47 uF, 10 V, +/- 10%, X7R, AEC-Q200 Grade 1, 0402"
C21: library part CMP-0006995-4, "CAP, CERM, 470 pF, 100 V, +/- 5%, C0G/NP0, 0603"
C24: library part CMP-0076706-1, "CAP, CERM, 4.7 µF, 25 V,+/- 10%, X7R, AEC-Q200 Grade 1, 0805"
C25 C27 C28 C33 C59 C63 C64 C70 C505: library part CMP-0007094-5, "CAP, CERM, 0.22 uF, 50 V, +/- 10%, X7R, AEC-Q200 Grade 1, 0603"
C29: library part CMP-0083840-1, "CAP, CERM, 4.7 pF, 50 V,+/- 5.3%, C0G/NP0, AEC-Q200 Grade 1, 0402"
C30 C31 C32 C43 C44 C45 C46 C47 C513 C521 C554: library part CMP-0007008-1, "CAP, CERM, 3.3 uF, 25 V, +/- 10%, X5R, 0603"
C34 C37 C504: library part CMP-0007139-4, "CAP, CERM, 1 uF, 25 V, +/- 10%, X7R, AEC-Q200 Grade 1, 0603"
C39: library part CMP-0088003-2, "CAP CER 22UF 10V X7S 1206"
C40: library part CMP-0006317-2, "CAP, CERM, 2200 pF, 50 V, +/- 10%, X7R, AEC-Q200 Grade 1, 0402"
C41 C42 C49 C50 C56 C57 C71: library part CMP-0861000-1, "CAP, CERM, 0.1 µF, 25 V,+/- 10%, X8L, AEC-Q200 Grade 0, 0402"
C52 C53 C58: library part CMP-0084284-1, "CAP, CERM, 2.2 µF, 10 V,+/- 10%, X7R, AEC-Q200 Grade 1, 0603"
C55 C60 C61 C62: library part CMP-0006350-2, "CAP, CERM, 0.1 uF, 10 V, +/- 10%, X7R, AEC-Q200 Grade 1, 0402"
C72: library part CMP-0006416-2, "CAP, CERM, 120 pF, 50 V, +/- 1%, C0G/NP0, 0402"
D1 D9 D10 D501: library part CMP-0079598-2, "Diode, Schottky, 30 V, 0.5 A, AEC-Q101, SOD-323"
D2 D5 D6: library part CMP-0092845-1, "LED Uni-Color Red 643nm 2-Pin Chip 0603(1608Metric) T/R"
D3: library part CMP-0028830-2, "Diode, Schottky, 40 V, 2 A, AEC-Q101, SOT-26"
D4: library part CMP-0028814-3, "Diode, Schottky, 20 V, 1.1 A, AEC-Q101, DO-219AB"
D7: library part CMP-0086617-1, "Diode Array 2 Pair Series Connection Schottky 30V 200mA (DC) Surface Mount 6-TSSOP, SC-88, SOT-363"
D8: library part CMP-0085730-1, "Diode, Zener, 3.3 V, 300 mW, AEC-Q101, SOD-323"
D500: library part CMP-0077948-2, "Diode, Schottky, 40 V, 5 A, AEC-Q101, SMC"
FB2: library part CMP-0089199-1, "120 Ohms @ 100MHz 1  Ferrite Bead 0603 (1608 Metric) 2A 40mOhm"
FID1 FID2 FID3 FID4 FID5 FID6: library part CMP-0077181-1, "Fiducial mark.  There is nothing to buy or mount."
H1 H2 H3 H4: library part CMP-0003617-1, "Machine Screw, Round, #4-40 x 1/4, Nylon, Philips panhead"
H500 H501 H502 H503: library part CMP-0003610-1, "Standoff, Hex, 0.5\"L #4-40 Nylon"
J1: library part CMP-0055800-1, "Power Jack, 2.1x5.5mm, R/A, TH"
J2: library part CMP-0090189-1, "6 Position FFC, FPC Connector Contacts, Bottom 0.039\" (1.00mm) Surface Mount, Right Angle from Molex"
J3 J4 J5 J6: library part CMP-0055332-1, "Header, 2.54mm, 3x1, Tin, TH"
J7: library part CMP-0055393-3, "Standard Banana Jack, insulated, 10A, red"
J8: library part CMP-0055389-3, "Standard Banana Jack, insulated, 10A, black"
J9: library part CMP-0087816-2, "NTERPOSER, 56 CONTACT, HOLE DATUM"
J10: library part CMP-0075593-2, "Header, 2.54mm, 4x2, Gold, SMT"
J11: library part CMP-0089821-1, "Connector Header Through Hole 10 position 0.100\" (2.54mm)"
J12: library part CMP-0092119-1, "Connector Header Surface Mount 20 position 0.050\" (1.27mm)"
J13: library part CMP-0081743-1, "Receptacle, 1.27mm, 10x2, Gold with Tin tail, SMT"
J14 J15: library part CMP-0077240-1, "Receptacle, 1.27mm, 8x2, Gold, SMT"
J16: library part CMP-0075409-2, "Header, 100mil, 4x1, Gold, TH"
L1: library part CMP-0061454-2, "Inductor, Shielded, Ferrite, 15 uH, 8.7 A, 0.019 ohm, SMD"
L2 L3: library part CMP-0061001-2, "Inductor, Shielded, Composite, 2.2 µH, 9.2 A, 0.01 ohm, AEC-Q200 Grade 1, SMD"
L4: library part CMP-0085685-1, "Inductor, Semi-Shielded, Ferrite, 22 µH, 1.5 A, 0.1476 ohm, AEC-Q200 Grade 1, SMD"
L5: library part CMP-0082247-1, "Inductor, Shielded, Ferrite, 2.2 µH, 0.7 A, 0.364 ohm, SMD"
L6: library part CMP-0058987-1, "Inductor, Shielded, 4.7 uH, 2.7 A, 0.083 ohm, AEC-Q200 Grade 1, SMD"
LBL1: library part CMP-0003625-1, "Thermal Transfer Printable Labels, 0.650\" W x 0.200\" H - 10,000 per roll"
Logo1: library part CMP-0074847-1, "FCC_disclaimer"
Logo2: library part CMP-0074838-1, "Texas Instrument Corporate Signature"
Logo3: library part CMP-0074769-1
Logo4: library part CMP-0074844-1
Q1 Q4: library part CMP-0077941-1, "MOSFET, 2-CH, N-CH, 30 V, 7.7 A, AEC-Q101, U-DFN2020-6"
Q2: library part CMP-0088579-4, "MOSFET 2N-CH 30V 0.35A 6TSSOP"
Q3: library part CMP-0082233-2, "MOSFET, 2-CH, N/P-CH, -30 V, -0.2 A, AEC-Q101, SOT-363"
R1: library part CMP-0022064-1, "RES, 158 k, 1%, 0.1 W, 0603"
R2: library part CMP-0021990-4, "RES, 100 k, 1%, 0.1 W, AEC-Q200 Grade 0, 0603"
R3: library part CMP-0093627-1, "Thick Film Chip Resistors 0603 316kO 0.1W 1% 100ppm/°C"
R4 R13 R31 R32 R49 R51: library part CMP-0026858-5, "RES, 1.8 k, 5%, 0.063 W, AEC-Q200 Grade 0, 0402"
R5 R10 R22 R28: library part CMP-0021521-3, "RES, 100 k, 1%, 0.125 W, AEC-Q200 Grade 0, 0805"
R6: library part CMP-0022844-4, "RES, 180 k, 1%, 0.1 W, 0603"
R7: library part CMP-0023267-5, "RES, 75.0 k, 1%, 0.1 W, 0603"
R8: library part CMP-0022808-4, "RES, 150 k, 1%, 0.1 W, 0603"
R9: library part CMP-0023184-4, "RES, 562 k, 1%, 0.1 W, 0603"
R11: library part CMP-0015168-2, "RES, 0.11, 1%, 0.5 W, 1210"
R12: library part CMP-0023308-5, "RES, 8.20 k, 1%, 0.1 W, 0603"
R14 R30 R50: library part CMP-0026917-5, "RES, 3.0 k, 5%, 0.063 W, AEC-Q200 Grade 0, 0402"
R15: library part CMP-0017552-3, "RES, 3.48 k, 1%, 0.25 W, AEC-Q200 Grade 0, 1206"
R16 R76 R520: library part CMP-0027002-2, "RES, 0, 5%, 0.063 W, 0402"
R17: library part CMP-0088626-1, "Res Thin Film 0402 8.2K Ohm 0.1% 0.063W(1/16W) ±25ppm/C Pad SMD Automotive T/R"
R18 R23 R25 R26 R29 R47 R63 R65 R67 R70 R82 R85 R86 R505: library part CMP-0027019-1, "RES, 10 k, 5%, 0.05 W, 0201"
R19 R20 R504: library part CMP-0088648-1, "Res Thin Film 0402 100K Ohm 0.1% 1/16W ±25ppm/°C Molded SMD SMD Punched Carrier T/R"
R21: library part CMP-0088630-1, "Res Thin Film 0402 15.6K Ohm 0.1% 1/10W ±25ppm/°C Molded SMD Paper T/R"
R24 R27: library part CMP-0020843-1, "RES, 10.2 k, 1%, 0.125 W, 0805"
R33: library part CMP-0026298-2, "RES, 33.2 k, 1%, 0.063 W, AEC-Q200 Grade 0, 0402"
R34 R35 R43 R44 R45 R66 R69 R72 R532: library part CMP-0025701-1, "RES, 10 k, 5%, 0.1 W, 0603"
R36: library part CMP-0023147-2, "RES, 4.32 k, 1%, 0.1 W, 0603"
R37 R39 R48 R64 R68 R71: library part CMP-0078193-1, "RES, 1.0 k, 5%, 0.1 W, AEC-Q200 Grade 0, 0402"
R38: library part CMP-0026839-3, "RES, 13, 5%, 0.063 W, AEC-Q200 Grade 0, 0402"
R40 R77: library part CMP-0026994-4, "RES, 10 k, 5%, 0.1 W, AEC-Q200 Grade 0, 0402"
R41 R42: library part CMP-0026916-3, "RES, 39, 5%, 0.063 W, AEC-Q200 Grade 0, 0402"
R46: library part CMP-0022707-2, "RES, 49.9, 1%, 0.1 W, AEC-Q200 Grade 0, 0603"
R62: library part CMP-0026240-2, "RES, 2.32 k, 1%, 0.063 W, AEC-Q200 Grade 0, 0402"
R73 R519: library part CMP-0025958-2, "RES, 10.0 k, 1%, 0.063 W, 0402"
R74: library part CMP-0089632-1, "0 Ohms Jumper 0.125W, 1/8W Chip Resistor 0805 (2012 Metric) Automotive AEC-Q200 Thick Film"
R75 R78 R79 R80 R81: library part CMP-0026993-2, "RES, 100, 5%, 0.1 W, AEC-Q200 Grade 0, 0402"
R83 R84: library part CMP-0023188-5, "RES, 56.0, 1%, 0.1 W, 0603"
R500: library part CMP-0026371-2, "RES, 41.2 k, 1%, 0.063 W, AEC-Q200 Grade 0, 0402"
R503: library part CMP-0088636-1, "RES SMD 12.1KOHM 0.1% 1/16W 0402"
SH-J1 SH-J2 SH-J3 SH-J4 SH-J5 SH-J6 SH-J7 SH-J8: library part CMP-0078738-1, "Single Operation 2.54mm Pitch Open Top Jumper Socket"
TP1 TP4 TP5 TP6 TP7 TP8 TP10 TP11 TP12 TP17: library part CMP-0055138-1, "Test Point, Miniature, Black, TH"
TP2 TP3 TP13 TP14 TP15 TP16 TP18 TP19 TP20 TP21 TP22 TP23: library part CMP-0003719-1, "Testpoint"
TP9: library part CMP-0055138-2, "Test Point, Miniature, Black, TH"
U1: library part CMP-0091061-1, "100-V Input, 3.5-A Non-Synchronous Buck DC/DC Converter with Ultra-low IQ"
U2 U3: library part CMP-0083641-1, "TPS62130A-Q1 3 to 17-V 3-A Automotive Step-Down Converter in 3 × 3 QFN Package, RGT0016C (VQFN-16)"
U4: library part CMP-0071334-1, "2MHz, 600mA Step-Down DC-DC Converter, 5-pin Micro SMD, Pb-Free"
U5: library part CMP-0073710-1, "2A LED Driver with Integrated NFET, High-Side Current Sense, and Shunt PWM Dimming Capable, DGQ0010E (VSSOP-10)"
U6: library part CMP-0051803-1, "Automotive Catalog Dual 2-Input Positive-AND Gate, DCT0008A, LARGE T&R"
U7: library part CMP-0093537-1, "FLASH - NOR Memory IC 128Mb (16M x 8) SPI - Quad I/O 133 MHz 8-WSON (6x8)"
U8: library part CMP-0081409-1, "Automotive Low-Quiescent-Current 1% Accurate Supervisor With Programmable Delay, DSE0006A (WSON-6)"
U9: library part CMP-0034937-2, "Dimmable Quasi-Resonant LED Lighting Controller, 9 to 21.5 V, -40 to 140 degC, 16-pin SOP (PW16), Green (RoHS & no Sb/Br)"
U10: library part CMP-0051598-1, "Automotive Catalog Single 2-Input Positive-OR Gate, DBV0005A, LARGE T&R"
U11: library part CMP-0750051-1, "Overvoltage and Undervoltage Reset IC With Time Delay and Manual Reset, DSE0006A (WSON-6)"
U12: library part CMP-0093674-1, "Sitara™ Microcontrollers"
U13 U16: library part CMP-0065229-3, "Asynchronous Communication Between Data Buses, RHL0024A (VQFN-24)"
U14: library part CMP-0051688-3, "Automotive Catalog Single Inverter Gate, DBV0005A (SOT-23-5)"
U15: library part CMP-0088841-1, "e.MMC Memory, 8GB NOR FLASH memory"
U17: library part CMP-0082079-1, "Automotive Single Schmitt-Trigger Inverter, DCK0005A (SOT-SC70-5)"
U18: library part CMP-0095233-1, "Four channel unidirectional level shifter 14-WQFN -40 to 125"
U19: library part CMP-0860382-1, "SN74AXC2T245RSW, RSW0010A (UQFN-10)"
U20: library part CMP-0860295-1, "Automotive Catalog Single 5-Ohm SP3T Analog Switch 5-V/3.3-V 3:1 Analog Multiplexer/Demultiplexer, DCU0008A (VSSOP-8)"
U21: library part CMP-0860146-1, "Automotive Grade, Remote and Local Temperature Sensor with N-Factor and Series-R Correction, DGK0008A (VSSOP-8)"
U22: library part CMP-0861099-1, "Automotive high-input voltage supervisor with manual reset and programmable-reset time delay, DBV0005A (SOT-23-5)"
Y1: library part CMP-0082061-2, "Oscillator, 25 MHz, 15 pF, SMD"
ZZ1: library part CMP-0003616-3
ZZ2: library part CMP-0077236-1
ZZ3: library part CMP-0077237-1
ZZ4 ZZ5: library part CMP-0077238-1

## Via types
v1: diameter 20, hole 10, Top Layer to Bottom Layer, tented top, 593 vias
v2: diameter 16, hole 8, Top Layer to Bottom Layer, tented both sides, 126 vias
v3: diameter 16, hole 8.01, Top Layer to Bottom Layer, tented top, 63 vias
v4: diameter 19.68, hole 7.87, Top Layer to Bottom Layer, 37 vias
v5: diameter 16, hole 8.02, Top Layer to Bottom Layer, tented bottom, 22 vias
v6: diameter 24.8, hole 12.99, Top Layer to Bottom Layer, 6 vias
v7: diameter 19.68, hole 7.87, Top Layer to Bottom Layer, tented both sides, 6 vias

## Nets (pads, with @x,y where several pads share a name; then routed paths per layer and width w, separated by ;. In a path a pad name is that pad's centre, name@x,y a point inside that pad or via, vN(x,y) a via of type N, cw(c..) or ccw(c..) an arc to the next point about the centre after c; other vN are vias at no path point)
1V2_EN: U3.13 U6.3 | length 1527.1
  Top Layer w9.4: U3.13@2645.51,2380.32 2645.51,2366.91 v1(2659.09,2353.32)
  Top Layer w10: v1(1673.59,1576.12) 1687.5,1590.03 U6.3@1715,1590.03
  SIGNAL1 w10: v1(1673.59,1576.12) 1993.91,1896.44 2441.01,1896.44 2590.84,2046.27 2590.84,2285.07 v1(2659.09,2353.32)
1V2_OB: C11.1 J3.1 L3.2 R7.2 U3.7 U3.14 | length 796.8
  Top Layer w9.4: v1(2478.68,2388.45) 2490.24,2400.01 U3.7@2535.27,2400.01 ; U3.14@2645.51,2400.01 2811.09,2400.01 L3.2@2812.21,2398.89 ; v1(2752.64,2253.62) 2755.5,2253.62 2764.04,2262.16 2798.38,2262.16 C11.1@2812.38,2276.16 2812.21,2276.34 2798.38,2290.16 2762.44,2290.16 2755.5,2297.1 v1(2752.64,2297.1)
  Top Layer w11.81: C11.1@2812.21,2276.34 L3.2@2812.21,2398.89 ; C11.1@2812.38,2276.16 R7.2@2812.38,2184.26 2813.37,2184.26 2826.16,2171.46 2826.16,2103.11 2851.54,2077.73 J3.1@2851.54,1984.78
1V2_PG: R10.1 U3.4 U6.1 | length 172.6
  Top Layer w9.4: v1(2539.89,2502.61) 2560.86,2481.64 U3.4@2560.86,2464.97
  Top Layer w10: U6.1@1715,1641.21 v1(1715,1669.08)
  Top Layer w14.5: v1(1667.92,1656.58) 1683.29,1641.21 U6.1@1715,1641.21
  Top Layer w15: R10.1@2656.86,2112.99 v1(2701.86,2112.99)
3V3_EN: U2.13 U10.4 | length 1447.5
  Top Layer w9.4: U2.13@1904.68,2380.32 1904.68,2366.91 v1(1918.26,2353.32)
  Top Layer w10: U10.4@1822.31,1314.67 v1(1864.7,1314.67)
  Bottom Layer w9.4: v1(1864.7,1314.67) 1689,1314.67 1640.21,1363.46 1640.21,1643.4 1612.8,1670.81 1612.8,1777.1 1878.85,2043.15 1878.85,2313.91 v1(1918.26,2353.32)
3V3_OB: C16.1 J5.1 L2.2 R5.2 R9.2 U2.7 U2.14 | length 713.7
  Top Layer w6.5: L2.2@1925.38,2612.48 1925.38,2567.16 L2.2@1945.13,2547.41 ; R5.2@2007.02,2547.41 R5.2@2018.69,2535.74 2089.84,2535.74 R9.2@2095.46,2530.13 ; C16.1@2052.94,2349.07 C16.1@2067.21,2349.07
  Top Layer w9.4: v1(1737.85,2388.45) 1749.41,2400.01 U2.7@1794.44,2400.01
  Top Layer w10: U2.14@1904.68,2400.01 1964.6,2400.01 ; C16.1@2015.54,2349.07 C16.1@2052.94,2349.07 2056.54,2345.47 J5.1@2056.54,1978.66
  other v1: 1999.22,2408.28 1999.22,2442.38 1999.22,2476.48
3V3_PG: R5.1 U2.4 U6.5 | length 143.6
  Top Layer w9.4: v1(1799.06,2502.61) 1820.03,2481.64 U2.4@1820.03,2464.97
  Top Layer w14: v1(1870.52,1536.56) U6.5@1870.52,1564.44
  Top Layer w14.5: U6.5@1870.52,1564.44 1902.23,1564.44 v1(1917.6,1549.07) ; v1@1990.7,2665.22 v1(1990.7,2666.71) ; R5.1@2012.19,2615.74 R5.1@2018.69,2615.74 R5.1@2025.19,2615.74 ; v1@2056.31,2665.22 v1(2056.31,2666.71)
5V: C7.1 C14.1 C26.1 C69.1 C503.1 C506.1 J6.2 J11.4 J11.6 J13.1 J15.1 R22.2 R24.2 R28.2 R519.2 TP4.1 U2.10 U2.11 U2.12 U8.3 U8.4 U10.5 U11.2 U11.6 U22.2 | length 780.8
  Top Layer w6.5: J6.2@1611.54,1978.66 1681.37,2048.49 1795.33,2048.49 1878.65,1965.17 C69.1@1878.65,1912.3
  Top Layer w9.4: 1828.26,2311.39 1839.72,2322.85 U2.10@1839.72,2354.73 ; C7.1@1859.4,2297.27 1859.4,2311.58 ; U2.11@1859.4,2354.73 1859.38,2311.58 ; U2.12@1879.09,2354.73 1879.09,2331.27 1859.4,2311.58
  Top Layer w10: 1447.44,1267.34 U11.6@1471.24,1267.34 1471.24,1283.96 1462.34,1292.86 1450.87,1292.86 ; U11.2@1490.93,1220.1 1490.93,1179.45 v1(1493.44,1176.94)
  Top Layer w20: U22.2@1875.94,1858.29 1875.94,1866.16 1878.65,1868.87 C69.1@1878.65,1912.3
  Top Layer w25: 1448.44,1403.87 1448.44,1421.34 ; 1495.69,1403.87 1495.69,1421.34
  Bottom Layer w20: v1(2386.96,375.92) R519.2@2386.96,417.66
  other v1: 3569.94,-155.83 2902.34,-117.15 3569.94,-112.52 2902.34,-73.84 3569.94,-69.21 2902.34,-30.53 1498.08,1137.13 1563.56,1137.13 1627.15,1137.13 1422.17,1341.11 1481.04,1341.11 1421.58,1386.77 1513.76,1386.77 1835.37,1436.79 1835.37,1481.47 1679.58,2154.04 1738.48,2154.04 1787.38,2154.04 1840.3,2154.04 1679.58,2217.29 1738.48,2217.29 1787.38,2217.29 1818.94,2297.9
5V_FB: C2.2 R2.2 R3.1 U1.5
  other v1: 891.61,2393.23 936.4,2393.23 904.05,2640.61 948.85,2640.61 878.18,2707.49 878.18,2752.28
5V_OB: C3.1 C15.1 J6.1 L1.2 R3.2
5V_SW: C1.2 D500.1 L1.1 R1.1 U1.8
  other v1: 1014.03,2801 1088.82,2801 1163.62,2801 570.24,2864.4 635.03,2864.4 1014.03,2875.8 1088.82,2875.8 1163.62,2875.8 540.24,2894.19 605.03,2894.19
B_LED_IADJ_PWM: R50.1 U12.C2 | length 1054.1
  Top Layer w6.5: v2(2503.4,1083.56) 2503.4,1083.45 2518.58,1068.28 U12.C2@2518.58,1068.17 ; v1(3232.14,1447.56) 3234.72,1450.14 3234.72,1460.11 3240.8,1466.2 R50.1@3240.8,1506.89
  SIGNAL2 w6.5: v2(2503.4,1083.56) 2481.68,1105.28 2481.68,1128.62 2498.78,1145.72 2498.78,1193.18 2531.89,1226.29 2544.13,1226.29 2660.22,1342.38 3128.39,1342.38 v1@3236.16,1450.16
BLUE_CATH: D10.2 J2.6 J16.4 Q4.3 Q4.8 | length 704.8
  Top Layer w6.5: Q4.3@4272.35,2231.59 Q4.3@4273.57,2232.81
  Top Layer w15: Q4.3@4273.57,2232.81 Q4.8@4306.38,2232.81 ; Q4.8@4307.78,2236.51 4308.27,2236.02 4308.27,2210.98 4328.36,2190.89 4381.43,2190.89 4412.25,2221.7 ; D10.2@4412.25,2246.3 4412.25,2221.7 ; J16.4@4646.25,2107.62 4526.33,2107.62 4412.25,2221.7
  Bottom Layer w6.5: J2.6@4454.68,2160.94 J2.6@4466.49,2160.94
  Bottom Layer w15: J2.6@4466.49,2160.94 4519.8,2107.62 J16.4@4646.25,2107.62
BLUE_LED_EN: R81.1 U12.M1 | length 3404.6
  Top Layer w6.5: v1(2409.95,784.7) U12.M1@2487.08,784.7 ; v1(4230.97,1971.88) 4230.97,1975.54 4235.92,1980.48 4235.92,1994.15 R81.1@4242.51,2000.74
  SIGNAL2 w6.5: v1(2409.95,784.7) 2337.31,857.34 2337.31,1501.1 2439.26,1603.05 2680.47,1603.05 2725.26,1558.26 3430.97,1558.26 ; 3431.02,1558.21 3430.97,1558.26 ; v1(4230.97,1971.88) 4230.97,1948.2 4240.76,1938.41 4281.46,1938.41 4292.56,1949.51 4292.56,1989.94 4225.84,2056.66 3807.02,2056.66 3634.43,1884.07 3634.43,1606.07 3586.62,1558.26 3430.97,1558.26
BROWNOUT_RST: R77.1 U12.A10 U22.1 | length 1431.5
  Top Layer w6.5: R77.1@1927.49,1911 1925.52,1911 1913.34,1898.82 U22.1@1913.34,1858.29 1913.34,1850.41 2150.55,1613.21 2617.01,1613.21 2783.55,1446.67 2783.55,1240.51 2763.79,1220.75 2763.79,1167.9 2763.79,1139.59 2770.55,1132.83 U12.A10@2770.55,1131.16
DAC_OUT: TP23.1 U12.T5 | length 153.6
  Top Layer w6.5: U12.T5@2613.07,658.27 U12.T5@2613.07,658.72 ; v3(2628.55,642.35) v3@2628.55,642.8
  Top Layer w10: U12.T5@2613.07,658.27 v3@2628.55,642.8
  Bottom Layer w10: v3(2628.55,642.35) 2628.55,528.65 TP23.1@2640.68,516.52
DMD_1V8: C42.2 C50.2 C52.1 C53.1 C55.1 C57.2 C58.1 C60.1 C61.1 C62.1 J4.2 J9.A5 J9.B12 J9.C14 J9.D12 J9.F13 J9.G3 R65.2 TP7.1 U13.23 U13.24 U16.23 U16.24 U19.6 | length 417.8
  Top Layer w7: U19.6@3470.73,265.67 3490.4,265.67 3494.93,261.15 v1(3494.93,246.28)
  Top Layer w10: v1(3494.93,246.28) C57.2@3532.29,246.28 ; v1@3909.25,184.4 3909.7,183.95 3909.7,162.92 J9.B12@3910.15,162.48 ; v1@3988.59,184.55 3988.74,184.4 3988.74,162.62 J9.D12@3988.89,162.48
  Top Layer w19.68: R65.2@3729.99,432.16 3735.9,438.07 C55.1@3767.94,438.07 3794.97,438.07 ; v1(3797.71,409.67) v1(3797.71,409.67) 3797.65,435.38 3794.97,438.07 ; J9.A5@3871.02,438.07 J9.A5@3870.78,438.07 3794.97,438.07 ; v1(4183.78,84.03) 4183.84,84.09 4190.74,84.09 4209.83,103.18 C60.1@4211.8,103.18 ; v1(4213.99,199.64) 4214.05,199.58 4214.05,164.73 C58.1@4215.74,163.04
  Top Layer w29: J9.G3@4107,516.81 4155.75,516.81
  other v1: 3799.96,41.32 3799.96,119.53 3909.25,181.73 3988.59,181.73 4252.41,485.92 4252.41,547.57 3504.97,746.65 3504.97,1161.3
  other v5: 3949.52,83.74 4067.63,123.11
DMD_1V8_OB: C12.1 J4.1 L5.2 U4.C3 | length 63
  Top Layer w10: 3239.65,2212.06 3239.65,2238.27 ; U4.C3@3239.65,2253.67 3239.65,2238.27 ; 3254.78,2223.14 3239.65,2238.27
DMD_D0: U12.F18 U13.3 | length 423.8
  Top Layer w6.5: U12.F18@3022.52,973.68 3032.3,973.68 3047.17,988.55 v1(3067.46,988.55) ; v1(3350.94,1060.17) 3364.93,1046.19 U13.3@3382.11,1046.19
  SIGNAL2 w6.5: v1(3067.46,988.55) 3073.74,988.55 3158.08,988.55 3256.96,1087.43 3323.69,1087.43 v1(3350.94,1060.17)
DMD_D0_1v8: J9.A2 U13.21 | length 1267.1
  Top Layer w6.5: U13.21@3512.03,1027.49 3558.88,1027.49 v1(3591.2,1059.81) ; v1(3811.01,556.18) J9.A2@3870.78,556.18
  SIGNAL2 w6.5: v1(3591.2,1059.81) 3606.95,1075.56 3659.95,1075.56 3732.17,1003.34 3732.17,948.49 3737.16,943.49 3789.25,943.49 3793.06,939.69 3793.06,922.71 3788.07,917.72 3735.98,917.72 3732.17,913.92 3732.17,896.94 3737.16,891.95 3789.25,891.95 3793.06,888.14 3793.06,871.17 3788.07,866.18 3735.98,866.18 3732.17,862.37 3732.17,844.35 3737.16,839.36 3788.75,839.36 3792.56,835.55 3792.56,818.57 3788.75,814.77 3737.16,814.77 3732.17,809.78 3732.17,799.64 3738.23,793.58 3752.38,793.58 3761.73,784.24 3761.73,720.15 3770.29,711.59 3770.29,667.91 3779.58,658.61 3855.35,658.61 3864.95,649.01 3864.95,564.41 3856.72,556.18 v1(3811.01,556.18)
DMD_D1: U12.G16 U13.4 | length 599.9
  Top Layer w6.5: U12.G16@2959.53,942.18 v2(2975.27,957.93) ; v1@3306.94,1064.49 3344.93,1026.5 U13.4@3382.11,1026.5
  SIGNAL2 w6.5: v2(2975.27,957.93) 3006.19,927.01 3210.71,927.01 3261.16,977.47 3317.1,977.47 3341.18,1001.55 3341.18,1030.25 v1@3306.94,1064.49
  other v1: 3307.16,1064.71
DMD_D1_1v8: J9.A4 U13.20 | length 1026.5
  Top Layer w6.5: U13.20@3512.03,1007.8 3575.47,1007.8 v1(3586.18,1018.51) ; v1(3791.81,493.73) 3808.1,477.44 3811.01,477.44 J9.A4@3870.78,477.44
  SIGNAL2 w6.5: v1(3586.18,1018.51) 3570.52,1018.51 3563.75,1011.73 3563.75,982.38 3570.55,975.57 3694.54,975.57 3716.49,953.63 3716.49,743.56 3754.63,705.42 3754.63,647.73 3759.62,642.74 3789.71,642.74 3793.51,638.94 3793.51,621.96 3788.52,616.97 3758.44,616.97 3754.63,613.16 3754.63,595.14 3759.62,590.15 3789.71,590.15 3793.51,586.34 3793.51,569.37 3789.71,565.56 3759.62,565.56 3754.63,560.57 3754.63,542.54 3760.73,536.44 3784.28,536.44 3788.09,532.64 3788.09,515.66 3784.28,511.86 3784.28,504.92 3791.81,497.38 v1(3791.81,493.73)
DMD_D2: U12.E17 U13.5 | length 446.3
  Top Layer w6.5: U12.E17@2991.02,1005.17 v2(3006.77,989.43) ; v1(3310.94,1020.8) 3324.93,1006.82 U13.5@3382.11,1006.82
  SIGNAL2 w6.5: v2(3006.77,989.43) 3031.29,964.91 3167.95,964.91 3235.41,1032.37 3299.38,1032.37 v1(3310.94,1020.8)
DMD_D2_1v8: J9.B2 U13.19 | length 1006.7
  Top Layer w6.5: U13.19@3512.03,988.12 3616.65,988.12 v1(3627.55,999.01) ; J9.B2@3910.15,556.18 v1(3910.15,590.94)
  SIGNAL1 w6.5: v1(3627.55,999.01) 3664.54,962.02 3671.02,962.02 3690.88,981.88 3696.27,981.88 3708.27,969.88 3708.27,962.82 3688.41,942.96 3688.41,937.57 3700.41,925.57 3707.47,925.57 3727.33,945.43 3732.71,945.43 3744.71,933.43 3744.71,926.37 3724.85,906.51 3724.85,901.13 3736.86,889.12 3743.91,889.12 3763.77,908.98 3769.16,908.98 3781.16,896.98 3781.16,889.93 3761.3,870.06 3761.3,864.68 3773.3,852.68 3780.36,852.68 3800.22,872.54 3805.61,872.54 3815.7,862.45 3815.7,857.06 3726.21,767.57 3726.21,748.34 3883.6,590.94 v1(3910.15,590.94)
DMD_D3: U12.E18 U13.6 | length 509.3
  Top Layer w6.5: v2(3006.77,1020.92) U12.E18@3022.52,1005.17 ; v1(3260.97,1005.15) 3286.91,1005.15 3304.93,987.13 U13.6@3382.11,987.13
  SIGNAL2 w5: 2994.72,970.45 2991.05,974.12 2991.05,1005.21 v2(3006.77,1020.92)
  SIGNAL2 w6.5: 2994.72,970.45 3018.06,947.11 3189.25,947.11 3247.29,1005.15 v1(3260.97,1005.15)
DMD_D3_1v8: J9.B3 U13.18 | length 1156.6
  Top Layer w6.5: U13.18@3512.03,968.43 3589.21,968.43 v1(3603.19,954.45)
  SIGNAL2 w6.5: v1(3603.19,954.45) 3691.01,954.45 3700.08,945.38 3700.08,720.51 3707.4,713.19 3724.72,713.19 3728.53,709.39 3728.53,692.41 3723.54,687.42 3700.45,687.42 3696.64,683.61 3696.64,666.64 3701.64,661.65 3729.72,661.65 3733.53,657.84 3733.53,640.87 3728.54,635.88 3700.45,635.88 3696.64,632.07 3696.64,615.1 3701.64,610.11 3729.72,610.11 3733.53,606.3 3733.53,589.33 3728.54,584.33 3700.45,584.33 3696.64,580.53 3696.64,562.5 3701.64,557.51 3733.22,557.51 3737.03,553.7 3737.03,536.73 3733.22,532.92 3701.64,532.92 3696.64,527.93 3696.64,509.91 3702.74,503.81 3730.29,503.81 3734.1,500 3734.1,478.68 3761.51,451.27 3832.47,451.27 3898,516.81 v5(3910.15,516.81)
